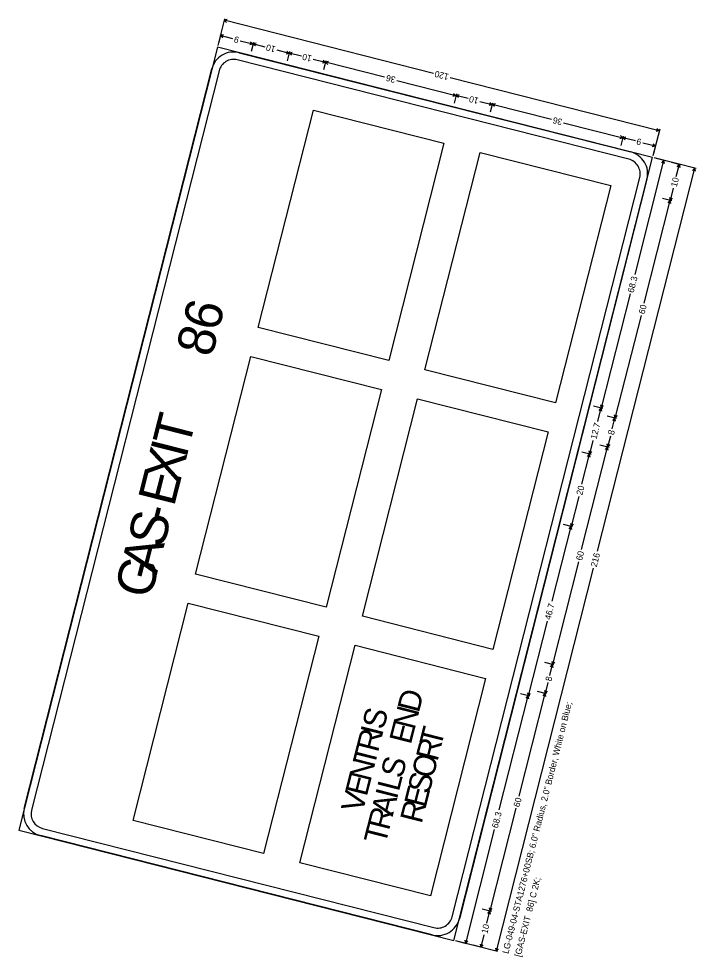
# Model space of a CAD drawing. Extents: x 670257 to 671518, y 737783 to 738188.
# Drawn here: x 670567.99 to 670594.4, y 738049.02 to 738085.62 of the extents above; entities that cross this region are included whole.
import ezdxf

# ---------------------------------------------------------------- set-up
doc = ezdxf.new("R2010")
doc.units = 0
doc.layers.add('R_SIGN', color=7, linetype='Continuous')

msp = doc.modelspace()

# ---------------------------------------------------------------- linework, layer by layer
at = {"layer": 'R_SIGN'}
for p, q in [((670576.016, 738085.621), (670575.751, 738084.574)), ((670576.122, 738085.588), (670576.001, 738085.561)), ((670584.161, 738083.492), (670576.001, 738085.561)), ((670576.094, 738085.481), (670576.001, 738085.561)), ((670575.864, 738085.023), (670575.773, 738084.664)), ((670575.97, 738084.989), (670575.849, 738084.963)), ((670576.343, 738084.838), (670575.849, 738084.963)), ((670575.943, 738084.882), (670575.849, 738084.963)), ((670576.627, 738084.766), (670577.121, 738084.64)), ((670577.001, 738084.614), (670577.121, 738084.64)), ((670577.028, 738084.721), (670577.121, 738084.64)), ((670577.137, 738084.7), (670577.046, 738084.341)), ((670577.242, 738084.667), (670577.121, 738084.64)), ((670577.602, 738084.518), (670577.121, 738084.64)), ((670577.215, 738084.56), (670577.121, 738084.64)), ((670578.054, 738084.404), (670578.535, 738084.282)), ((670578.414, 738084.255), (670578.535, 738084.282)), ((670578.442, 738084.362), (670578.535, 738084.282)), ((670578.55, 738084.342), (670578.459, 738083.983)), ((670578.656, 738084.308), (670578.535, 738084.282)), ((670579.016, 738084.16), (670578.535, 738084.282)), ((670578.628, 738084.201), (670578.535, 738084.282)), ((670579.468, 738084.045), (670579.949, 738083.923)), ((670579.828, 738083.897), (670579.949, 738083.923)), ((670579.855, 738084.004), (670579.949, 738083.923)), ((670579.964, 738083.983), (670579.873, 738083.624)), ((670580.069, 738083.95), (670579.949, 738083.923)), ((670582.255, 738083.338), (670579.949, 738083.923)), ((670580.042, 738083.843), (670579.949, 738083.923)), ((670582.731, 738083.217), (670585.037, 738082.633)), ((670584.804, 738083.328), (670592.964, 738081.259)), ((670584.944, 738082.713), (670585.037, 738082.633)), ((670585.053, 738082.692), (670584.962, 738082.333)), ((670585.158, 738082.659), (670585.037, 738082.633)), ((670584.917, 738082.606), (670585.037, 738082.633)), ((670585.518, 738082.511), (670585.037, 738082.633)), ((670585.131, 738082.552), (670585.037, 738082.633)), ((670585.97, 738082.396), (670586.451, 738082.274)), ((670586.331, 738082.248), (670586.451, 738082.274)), ((670586.358, 738082.355), (670586.451, 738082.274)), ((670586.466, 738082.334), (670586.375, 738081.975)), ((670586.572, 738082.301), (670586.451, 738082.274)), ((670588.757, 738081.689), (670586.451, 738082.274)), ((670586.545, 738082.194), (670586.451, 738082.274)), ((670577.325, 738073.58), (670579.476, 738082.061)), ((670579.476, 738082.061), (670584.565, 738080.77)), ((670589.234, 738081.568), (670591.54, 738080.983)), ((670592.979, 738081.319), (670592.714, 738080.272)), ((670592.843, 738081.233), (670592.964, 738081.259)), ((670592.87, 738081.34), (670592.964, 738081.259)), ((670591.419, 738080.957), (670591.54, 738080.983)), ((670591.447, 738081.064), (670591.54, 738080.983)), ((670591.555, 738081.043), (670591.464, 738080.684)), ((670591.555, 738081.043), (670591.464, 738080.684)), ((670591.661, 738081.01), (670591.54, 738080.983)), ((670592.034, 738080.858), (670591.54, 738080.983)), ((670591.633, 738080.903), (670591.54, 738080.983)), ((670584.565, 738080.77), (670582.414, 738072.289)), ((670592.318, 738080.786), (670592.812, 738080.661)), ((670592.692, 738080.634), (670592.812, 738080.661)), ((670592.719, 738080.741), (670592.812, 738080.661)), ((670592.827, 738080.721), (670592.736, 738080.362)), ((670583.828, 738071.93), (670585.979, 738080.412)), ((670585.979, 738080.412), (670591.068, 738079.121)), ((670592.02, 738075.653), (670593.147, 738080.098)), ((670594.403, 738079.78), (670592.758, 738080.197)), ((670593.207, 738080.083), (670592.848, 738080.174)), ((670593.066, 738080.005), (670593.147, 738080.098)), ((670593.173, 738079.978), (670593.147, 738080.098)), ((670590.557, 738064.865), (670594.344, 738079.795)), ((670593.805, 738079.931), (670593.446, 738080.022)), ((670593.623, 738079.466), (670593.745, 738079.947)), ((670593.665, 738079.853), (670593.745, 738079.947)), ((670593.772, 738079.826), (670593.745, 738079.947)), ((670594.263, 738079.701), (670594.344, 738079.795)), ((670594.37, 738079.674), (670594.344, 738079.795)), ((670591.068, 738079.121), (670588.917, 738070.64)), ((670593.509, 738079.014), (670593.387, 738078.533)), ((670593.36, 738078.654), (670593.387, 738078.533)), ((670593.467, 738078.626), (670593.387, 738078.533)), ((670592.372, 738074.53), (670593.387, 738078.533)), ((670593.447, 738078.518), (670593.088, 738078.609)), ((670593.447, 738078.518), (670593.088, 738078.609)), ((670593.306, 738078.44), (670593.387, 738078.533)), ((670593.413, 738078.412), (670593.387, 738078.533)), ((670591.826, 738074.888), (670590.698, 738070.444)), ((670592.251, 738074.055), (670591.236, 738070.052)), ((670582.414, 738072.289), (670577.325, 738073.58)), ((670574.887, 738063.967), (670577.038, 738072.449)), ((670577.038, 738072.449), (670582.127, 738071.158)), ((670588.917, 738070.64), (670583.828, 738071.93)), ((670582.127, 738071.158), (670579.976, 738062.677)), ((670581.39, 738062.318), (670583.541, 738070.8)), ((670583.541, 738070.8), (670588.63, 738069.509)), ((670590.672, 738070.564), (670590.698, 738070.444)), ((670590.758, 738070.428), (670590.399, 738070.519)), ((670590.758, 738070.428), (670590.399, 738070.519)), ((670590.565, 738069.916), (670590.698, 738070.444)), ((670590.618, 738070.35), (670590.698, 738070.444)), ((670590.779, 738070.537), (670590.698, 738070.444)), ((670590.725, 738070.323), (670590.698, 738070.444)), ((670591.296, 738070.036), (670590.937, 738070.127)), ((670591.128, 738069.629), (670591.236, 738070.052)), ((670591.155, 738069.958), (670591.236, 738070.052)), ((670591.209, 738070.172), (670591.236, 738070.052)), ((670591.316, 738070.145), (670591.236, 738070.052)), ((670591.262, 738069.931), (670591.236, 738070.052)), ((670588.63, 738069.509), (670586.479, 738061.027)), ((670590.377, 738069.176), (670590.243, 738068.648)), ((670591.056, 738069.344), (670590.949, 738068.921)), ((670589.934, 738064.918), (670590.949, 738068.921)), ((670590.217, 738068.769), (670590.243, 738068.648)), ((670590.324, 738068.742), (670590.243, 738068.648)), ((670591.009, 738068.905), (670590.65, 738068.997)), ((670590.868, 738068.827), (670590.949, 738068.921)), ((670590.923, 738069.041), (670590.949, 738068.921)), ((670591.03, 738069.014), (670590.949, 738068.921)), ((670590.975, 738068.8), (670590.949, 738068.921)), ((670590.303, 738068.633), (670589.944, 738068.724)), ((670589.945, 738067.474), (670590.243, 738068.648)), ((670590.162, 738068.555), (670590.243, 738068.648)), ((670590.269, 738068.528), (670590.243, 738068.648)), ((670589.824, 738066.996), (670589.526, 738065.821)), ((670588.787, 738062.907), (670589.526, 738065.821)), ((670589.586, 738065.806), (670589.227, 738065.897)), ((670589.445, 738065.728), (670589.526, 738065.821)), ((670589.5, 738065.942), (670589.526, 738065.821)), ((670589.607, 738065.915), (670589.526, 738065.821)), ((670589.552, 738065.701), (670589.526, 738065.821)), ((670589.813, 738064.442), (670588.798, 738060.439)), ((670590.386, 738064.191), (670586.6, 738049.262)), ((670579.976, 738062.677), (670574.887, 738063.967)), ((670572.449, 738054.355), (670574.6, 738062.836)), ((670574.6, 738062.836), (670579.689, 738061.546)), ((670586.479, 738061.027), (670581.39, 738062.318)), ((670588.591, 738062.134), (670587.852, 738059.22)), ((670579.689, 738061.546), (670577.538, 738053.064)), ((670578.952, 738052.706), (670581.103, 738061.187)), ((670581.103, 738061.187), (670586.192, 738059.897)), ((670588.858, 738060.424), (670588.499, 738060.515)), ((670588.69, 738060.016), (670588.798, 738060.439)), ((670588.717, 738060.346), (670588.798, 738060.439)), ((670588.771, 738060.56), (670588.798, 738060.439)), ((670588.878, 738060.533), (670588.798, 738060.439)), ((670588.824, 738060.319), (670588.798, 738060.439)), ((670586.192, 738059.897), (670584.041, 738051.415)), ((670588.618, 738059.731), (670588.511, 738059.308)), ((670586.724, 738054.775), (670587.852, 738059.22)), ((670587.496, 738055.305), (670588.511, 738059.308)), ((670587.912, 738059.205), (670587.553, 738059.296)), ((670587.771, 738059.126), (670587.852, 738059.22)), ((670587.825, 738059.34), (670587.852, 738059.22)), ((670587.932, 738059.313), (670587.852, 738059.22)), ((670587.878, 738059.099), (670587.852, 738059.22)), ((670588.571, 738059.293), (670588.212, 738059.384)), ((670588.43, 738059.215), (670588.511, 738059.308)), ((670588.485, 738059.429), (670588.511, 738059.308)), ((670588.592, 738059.402), (670588.511, 738059.308)), ((670588.537, 738059.188), (670588.511, 738059.308)), ((670587.375, 738054.83), (670586.36, 738050.827)), ((670577.538, 738053.064), (670572.449, 738054.355)), ((670586.53, 738054.01), (670585.403, 738049.565)), ((670584.041, 738051.415), (670578.952, 738052.706)), ((670586.42, 738050.812), (670586.061, 738050.903)), ((670586.238, 738050.346), (670586.36, 738050.827)), ((670586.279, 738050.733), (670586.36, 738050.827)), ((670586.334, 738050.947), (670586.36, 738050.827)), ((670586.441, 738050.92), (670586.36, 738050.827)), ((670586.386, 738050.706), (670586.36, 738050.827)), ((670586.123, 738049.894), (670586.001, 738049.413)), ((670586.659, 738049.246), (670585.014, 738049.664)), ((670585.463, 738049.55), (670585.104, 738049.641)), ((670585.377, 738049.686), (670585.403, 738049.565)), ((670585.484, 738049.658), (670585.403, 738049.565)), ((670586.061, 738049.398), (670585.702, 738049.489)), ((670585.975, 738049.534), (670586.001, 738049.413)), ((670586.082, 738049.507), (670586.001, 738049.413)), ((670586.573, 738049.382), (670586.6, 738049.262)), ((670586.68, 738049.355), (670586.6, 738049.262))]:
    msp.add_line(p, q, dxfattribs=at)
for points in [[(670584.954, 738049.679), (670592.698, 738080.212), (670575.735, 738084.514), (670567.991, 738053.981), (670584.954, 738049.679), (670584.954, 738049.679)], [(670576.584, 738084.299), (670591.85, 738080.427)], [(670591.779, 738080.144), (670576.512, 738084.016)], [(670568.207, 738054.829), (670575.52, 738083.666)], [(670575.803, 738083.594), (670568.489, 738054.757)], [(670584.887, 738050.599), (670592.201, 738079.436)], [(670592.483, 738079.364), (670585.17, 738050.527)], [(670584.106, 738049.894), (670568.84, 738053.766)], [(670568.911, 738054.049), (670584.178, 738050.177)]]:
    msp.add_lwpolyline(points, dxfattribs=at)
for centre, radius, start, end in [((670576.368, 738083.451), 0.875, 75.7686, 165.7688), ((670576.368, 738083.451), 0.583, 75.7686, 165.7688), ((670591.635, 738079.579), 0.583, 345.7686, 75.7688), ((670591.635, 738079.579), 0.875, 345.7686, 75.7688), ((670569.055, 738054.614), 0.875, 165.7688, 255.7684), ((670569.055, 738054.614), 0.583, 165.7688, 255.7684), ((670584.321, 738050.742), 0.875, 255.7684, 345.7686), ((670584.321, 738050.742), 0.583, 255.7684, 345.7686)]:
    msp.add_arc(centre, radius, start, end, dxfattribs=at)

# ---------------------------------------------------------------- texts
for s, height, rotation, p in [('9', 0.247, 165.7688, (670576.598, 738084.901)), ('10', 0.2469, 165.7688, (670578.025, 738084.539)), ('10', 0.2469, 165.7688, (670579.438, 738084.18)), ('36', 0.2469, 165.7688, (670582.702, 738083.352)), ('120', 0.2469, 165.7688, (670584.775, 738083.463)), ('10', 0.2469, 165.7688, (670585.941, 738082.531)), ('36', 0.2469, 165.7688, (670589.204, 738081.703)), ('9', 0.247, 165.7688, (670592.289, 738080.921)), ('10', 0.2469, 75.7686, (670593.644, 738079.043)), ('68.3', 0.2469, 75.7686, (670591.961, 738074.918)), ('6', 1.458, 75.7686, (670575.772, 738073.387)), ('60', 0.2469, 75.7686, (670592.386, 738074.084)), ('8', 1.458, 75.7686, (670575.517, 738072.383)), ('T', 1.458, 75.7686, (670574.617, 738068.835)), ('12.7', 0.2469, 75.7686, (670590.512, 738069.205)), ('8', 0.247, 75.7686, (670591.191, 738069.373)), ('I', 1.458, 75.7686, (670574.517, 738068.439)), ('X', 1.458, 75.7686, (670574.255, 738067.407)), ('E', 1.458, 75.7686, (670574.04, 738066.559)), ('20', 0.2469, 75.7686, (670589.959, 738067.025)), ('-', 1.458, 75.7686, (670573.864, 738065.867)), ('S', 1.458, 75.7686, (670573.631, 738064.948)), ('A', 1.458, 75.7686, (670573.37, 738063.916)), ('60', 0.2469, 75.7686, (670589.948, 738064.472)), ('216', 0.2469, 75.7686, (670590.521, 738064.221)), ('G', 1.458, 75.7686, (670573.126, 738062.955)), ('46.7', 0.2469, 75.7686, (670588.726, 738062.164)), ('8', 0.247, 75.7686, (670588.753, 738059.761)), ('D', 0.875, 75.7686, (670583.587, 738058.526)), ('LG-049-04-STA1276+00SB; 6.0" Radius, 2.0" Border, White on Blue; ', 0.24688, 75.7686, (670587.078, 738049.14)), ('S', 0.875, 75.7686, (670582.217, 738057.867)), ('N', 0.875, 75.7686, (670583.42, 738057.864)), ('E', 0.875, 75.7686, (670583.273, 738057.288)), ('R', 0.875, 75.7686, (670581.993, 738056.985)), ('I', 0.875, 75.7686, (670582.15, 738057.604)), ('T', 0.875, 75.7686, (670584.449, 738057.179)), ('R', 0.875, 75.7686, (670584.31, 738056.628)), ('T', 0.875, 75.7686, (670581.853, 738056.434)), ('N', 0.875, 75.7686, (670581.703, 738055.84)), ('S', 0.875, 75.7686, (670582.938, 738055.965)), ('O', 0.875, 75.7686, (670584.14, 738055.958)), ('E', 0.875, 75.7686, (670581.556, 738055.263)), ('L', 0.875, 75.7686, (670582.809, 738055.456)), ('S', 0.875, 75.7686, (670583.987, 738055.355)), ('V', 0.875, 75.7686, (670581.393, 738054.619)), ('I', 0.875, 75.7686, (670582.731, 738055.15)), ('E', 0.875, 75.7686, (670583.851, 738054.821)), ('A', 0.875, 75.7686, (670582.564, 738054.489)), ('60', 0.2469, 75.7686, (670587.51, 738054.859)), ('R', 0.875, 75.7686, (670582.424, 738053.937)), ('R', 0.875, 75.7686, (670583.694, 738054.202)), ('68.3', 0.2469, 75.7686, (670586.665, 738054.039)), ('T', 0.875, 75.7686, (670582.284, 738053.386)), ('[GAS-EXIT  86] C 2K; ', 0.24688, 75.7686, (670587.557, 738049.019)), ('10', 0.2469, 75.7686, (670586.258, 738049.924))]:
    msp.add_text(s, height=height, rotation=rotation, dxfattribs=at).set_placement(p)

doc.saveas('drawing.dxf')
